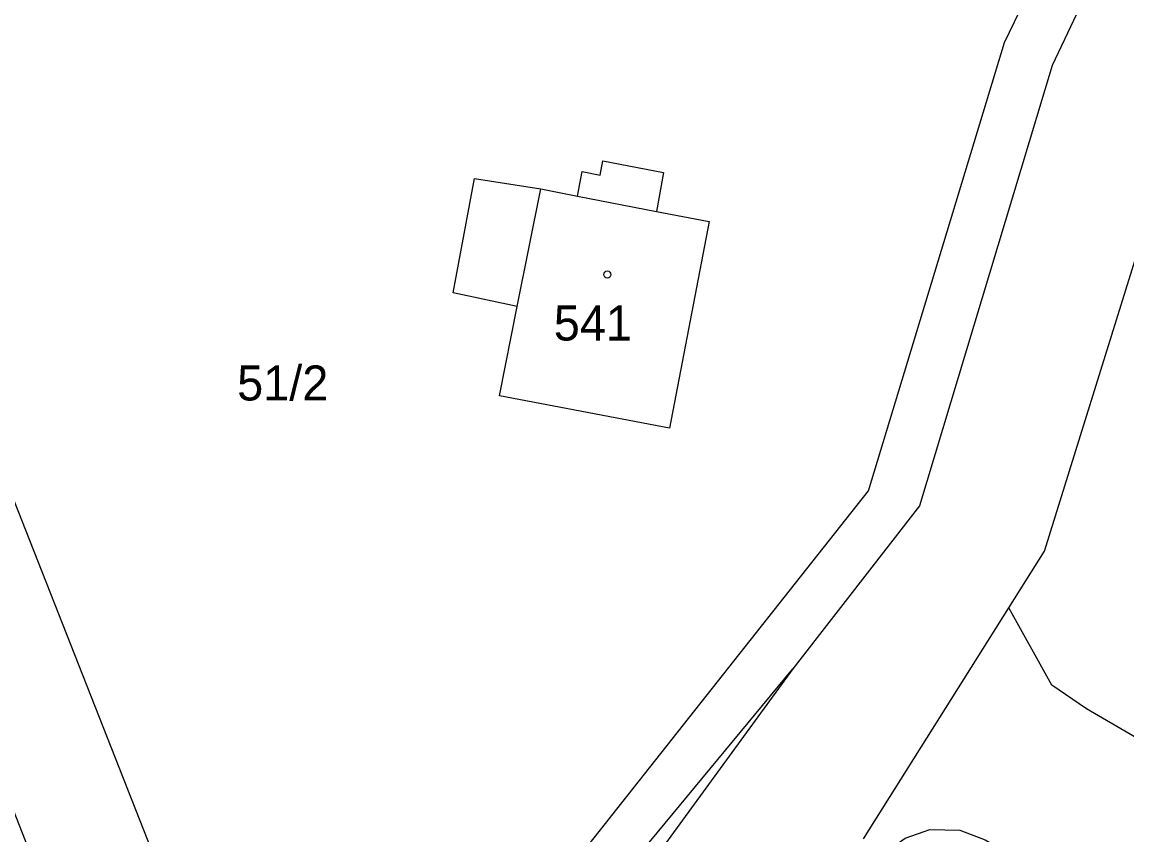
# Model space of a CAD drawing. Extents: x -553916 to -552953, y -1067470 to -1066637.
# Drawn here: x -553527.3 to -553473.7, y -1066947.3 to -1066907.8 of the extents above; entities that cross this region are included whole.
import ezdxf

# ---------------------------------------------------------------- set-up
doc = ezdxf.new("R2010")
doc.units = 0
for name, color, linetype in [('Hranice parcel', 7, 'Continuous'), ('Kolej', 7, 'Continuous'), ('Parcelní čísla', 7, 'Continuous'), ('Vnitřní kresba', 7, 'Continuous'), ('Vrstva 1', 7, 'Continuous'), ('Značky budov', 7, 'Continuous')]:
    doc.layers.add(name, color=color, linetype=linetype)

msp = doc.modelspace()

# ---------------------------------------------------------------- linework, layer by layer
at = {"layer": 'Hranice parcel'}
for p, q in [((-553486.47, -1066947.45), (-553479.42, -1066936.25)), ((-553514.13, -1066968.51), (-553489.9, -1066939.2))]:
    msp.add_line(p, q, dxfattribs=at)
for points in [[(-553468.58, -1066891.47), (-553477.31, -1066909.92), (-553483.75, -1066931.3), (-553489.9, -1066939.2)], [(-553515.05, -1066965.6), (-553502.53, -1066951.2), (-553486.22, -1066930.56), (-553479.63, -1066908.8), (-553477.16, -1066903.7)], [(-553495.88, -1066927.52), (-553504.13, -1066925.96), (-553503.27, -1066921.61), (-553506.38, -1066920.95), (-553505.35, -1066915.4), (-553502.13, -1066915.91), (-553500.34, -1066916.26), (-553500.12, -1066915.07), (-553499.24, -1066915.24), (-553499.11, -1066914.55), (-553496.17, -1066915.11), (-553496.51, -1066917), (-553493.96, -1066917.49), (-553495.88, -1066927.52)], [(-553479.42, -1066936.25), (-553477.68, -1066933.49), (-553473.2, -1066919.09)], [(-553444.09, -1066959.55), (-553475.65, -1066941.14), (-553477.33, -1066939.99), (-553479.42, -1066936.25)], [(-553489.9, -1066939.2), (-553506.21, -1066961.59), (-553507.62, -1066963.64), (-553510.49, -1066967.37), (-553513.35, -1066970.96)], [(-553485.37, -1066948.09), (-553484.44, -1066947.42), (-553483.24, -1066947.01), (-553481.79, -1066947.03), (-553480.57, -1066947.51), (-553464.25, -1066957.05)]]:
    msp.add_lwpolyline(points, dxfattribs=at)
at = {"layer": 'Kolej'}
msp.add_lwpolyline([(-553503.324, -1067065.808), (-553502.678, -1067054.027), (-553502.762, -1067041.504), (-553503.626, -1067029.057), (-553504.756, -1067019.974), (-553506.183, -1067011.388), (-553508.328, -1067001.388), (-553510.948, -1066991.622), (-553512.921, -1066985.291), (-553515.647, -1066977.347), (-553517.422, -1066972.53), (-553519.157, -1066967.95), (-553522.886, -1066958.375), (-553529.101, -1066942.549), (-553538.686, -1066918.107), (-553542.908, -1066907.329), (-553546.692, -1066897.676), (-553555.025, -1066876.441), (-553564.644, -1066851.894), (-553574.241, -1066827.427), (-553583.19, -1066804.618)], dxfattribs=at)
at = {"layer": 'Vnitřní kresba'}
for p, q in [((-553503.27, -1066921.61), (-553502.13, -1066915.91)), ((-553500.34, -1066916.26), (-553496.51, -1066917))]:
    msp.add_line(p, q, dxfattribs=at)
at = {"layer": 'Vrstva 1'}
msp.add_lwpolyline([(-553537.18, -1066906.98), (-553519.04, -1066953.03), (-553515.05, -1066965.6)], dxfattribs=at)
at = {"layer": 'Značky budov'}
msp.add_circle((-553498.897, -1066920.069), 0.175, dxfattribs=at)

# ---------------------------------------------------------------- texts
at = {"layer": 'Parcelní čísla'}
for s, p in [('541', (-553501.495, -1066923.269)), ('51/2', (-553516.859, -1066926.18))]:
    msp.add_text(s, height=1.7, dxfattribs=at).set_placement(p)

doc.saveas('drawing.dxf')
